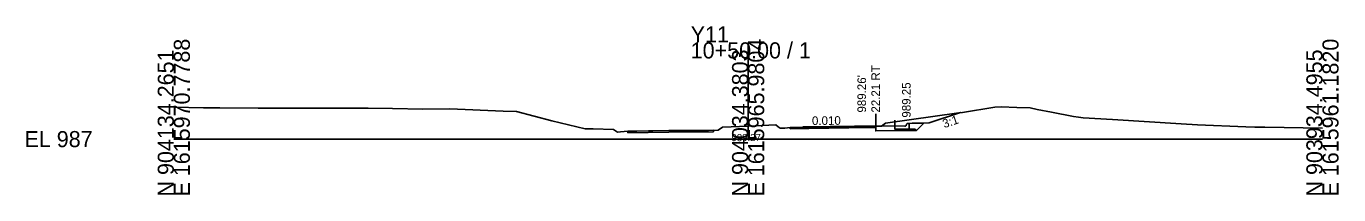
# Model space of a CAD drawing. Extents: x -26 to 203, y -10 to 2019.
# Drawn here: x -25.7 to 202.8, y 490.3 to 519.7 of the extents above; entities that cross this region are included whole.
import ezdxf

# ---------------------------------------------------------------- set-up
doc = ezdxf.new("R2010")
doc.units = 0
for name, color, linetype in [('Exist Cross Section Cell', 7, 'Continuous'), ('Exist XS Center Line Elevation Label', 7, 'Continuous'), ('Exist XS Ground Line', 7, 'Continuous'), ('Prop XS Dump Level', 7, 'Continuous'), ('Prop XS Earthwork Shape', 7, 'Continuous'), ('Prop XS EOT Tick Mark', 7, 'Continuous'), ('Prop XS Finish Grade', 7, 'Continuous'), ('Prop XS Finish Grade CurbGutter', 7, 'Continuous'), ('Prop XS Finish Grade Earthwork', 7, 'Continuous'), ('Prop XS Finish Grade Pavement', 7, 'Continuous'), ('Prop XS Hydro Elevations', 7, 'Continuous'), ('Prop XS Pvmt Edge Slope', 7, 'Continuous'), ('Prop XS Side Slope Text', 7, 'Continuous'), ('Prop XS Subgrade CurbGutter', 7, 'Continuous'), ('Prop XS Subgrade Earthwork', 7, 'Continuous')]:
    doc.layers.add(name, color=color, linetype=linetype)

msp = doc.modelspace()

# ---------------------------------------------------------------- linework, layer by layer
at = {"layer": 'Exist Cross Section Cell'}
for p, q in [((100, 500), (100, 516.85)), ((0, 500), (100, 500)), ((100, 500), (200, 500))]:
    msp.add_line(p, q, dxfattribs=at)
at = {"layer": 'Exist XS Ground Line'}
for p, q in [((0, 505.57), (5.16, 505.47)), ((5.16, 505.47), (8.01, 505.45)), ((8.01, 505.45), (14.71, 505.41)), ((14.71, 505.41), (18.03, 505.38)), ((18.03, 505.38), (21.67, 505.38)), ((21.67, 505.38), (28.04, 505.39)), ((28.04, 505.39), (33.82, 505.38)), ((33.82, 505.38), (38.05, 505.34)), ((38.05, 505.34), (43.37, 505.23)), ((43.37, 505.23), (48.06, 505.25)), ((48.06, 505.25), (57.33, 504.87)), ((137.34, 504.65), (142.98, 505.56)), ((142.98, 505.56), (144.07, 505.62)), ((144.07, 505.62), (146.78, 505.52)), ((146.78, 505.52), (149.12, 505.42)), ((149.12, 505.42), (150.33, 505.18)), ((150.33, 505.18), (152.8, 504.69)), ((57.33, 504.87), (59.65, 504.79)), ((59.65, 504.79), (65.82, 503.19)), ((65.82, 503.19), (71.65, 501.8)), ((123.25, 502.27), (123.93, 502.79)), ((123.93, 502.79), (136.66, 504.59)), ((136.66, 504.59), (137.34, 504.65)), ((152.8, 504.69), (156.67, 503.94)), ((156.67, 503.94), (157.55, 503.8)), ((157.55, 503.8), (158.33, 503.68)), ((158.33, 503.68), (163.46, 503.39)), ((163.46, 503.39), (175.39, 502.67)), ((71.65, 501.8), (73.02, 501.76)), ((73.02, 501.76), (76.57, 501.66)), ((76.57, 501.66), (77.25, 501.2)), ((77.25, 501.2), (77.75, 501.24)), ((77.75, 501.24), (79.04, 501.36)), ((79.04, 501.36), (80.63, 501.39)), ((80.63, 501.39), (86.21, 501.47)), ((86.21, 501.47), (93.08, 501.5)), ((93.08, 501.5), (94.81, 501.55)), ((94.81, 501.55), (95.52, 502.06)), ((95.52, 502.06), (100, 502.27)), ((100, 502.27), (104.84, 502.49)), ((104.84, 502.49), (105.22, 502.16)), ((105.22, 502.16), (105.59, 501.92)), ((105.59, 501.92), (106.37, 501.93)), ((106.37, 501.93), (107.33, 502.02)), ((107.33, 502.02), (110.58, 502.09)), ((110.58, 502.09), (114.26, 502.21)), ((114.26, 502.21), (118.54, 502.23)), ((118.54, 502.23), (121.5, 502.26)), ((121.5, 502.26), (122.21, 502.27)), ((122.21, 502.27), (123.25, 502.27)), ((175.39, 502.67), (178.22, 502.5)), ((178.22, 502.5), (186.67, 502.13)), ((186.67, 502.13), (188.23, 502.09)), ((188.23, 502.09), (189.95, 502.05)), ((189.95, 502.05), (200, 501.93))]:
    msp.add_line(p, q, dxfattribs=at)
at = {"layer": 'Prop XS Dump Level'}
msp.add_line((125.55, 502.3), (109.55, 502.14), dxfattribs=at)
at = {"layer": 'Prop XS Earthwork Shape'}
for points in [[(130.59, 502.79), (131.55, 502.81), (136.96, 504.61), (136.66, 504.59), (123.93, 502.79), (123.25, 502.27), (122.21, 502.27), (122.21, 501.43), (129.3, 501.5), (129.05, 501.75), (128.05, 501.74), (125.55, 501.72), (125.55, 502.3), (127.3, 502.24), (127.43, 502.27), (127.52, 502.36), (127.59, 502.61), (127.68, 502.7), (127.8, 502.74), (128.05, 502.74), (128.59, 502.75)], [(129.05, 501.75), (129.3, 501.5), (130.59, 502.79), (128.59, 502.75), (128.05, 502.74), (128.05, 501.74)], [(128.05, 501.74), (128.05, 502.74), (127.8, 502.74), (127.68, 502.7), (127.59, 502.61), (127.52, 502.36), (127.43, 502.27), (127.3, 502.24), (125.55, 502.3), (125.55, 501.72)]]:
    msp.add_lwpolyline(points, close=True, dxfattribs=at)
at = {"layer": 'Prop XS EOT Tick Mark'}
msp.add_line((125.55, 502.3), (125.55, 503.3), dxfattribs=at)
at = {"layer": 'Prop XS Finish Grade'}
msp.add_line((128.05, 502.74), (130.59, 502.79), dxfattribs=at)
at = {"layer": 'Prop XS Finish Grade CurbGutter'}
for p, q in [((125.55, 502.3), (127.3, 502.24)), ((127.3, 502.24), (127.43, 502.27)), ((127.43, 502.27), (127.52, 502.36)), ((127.52, 502.36), (127.59, 502.61)), ((127.59, 502.61), (127.68, 502.7)), ((127.8, 502.74), (127.68, 502.7)), ((128.05, 502.74), (127.8, 502.74))]:
    msp.add_line(p, q, dxfattribs=at)
at = {"layer": 'Prop XS Finish Grade Earthwork'}
for p, q in [((128.59, 502.75), (131.55, 502.81)), ((131.55, 502.81), (136.96, 504.61))]:
    msp.add_line(p, q, dxfattribs=at)
at = {"layer": 'Prop XS Finish Grade Pavement'}
for p, q in [((79.04, 501.36), (86.21, 501.47)), ((79.04, 501.36), (79.04, 501.11)), ((79.04, 501.11), (86.21, 501.22)), ((86.21, 501.47), (93.94, 501.53)), ((86.21, 501.22), (93.95, 501.28)), ((93.95, 501.28), (93.94, 501.53)), ((110.58, 502.09), (107.33, 502.02)), ((107.33, 502.02), (107.34, 501.77)), ((110.59, 501.84), (107.34, 501.77)), ((117.55, 502.22), (110.58, 502.09)), ((117.56, 501.97), (110.59, 501.84)), ((125.55, 502.29), (117.55, 502.22)), ((122.21, 502.01), (117.56, 501.97))]:
    msp.add_line(p, q, dxfattribs=at)
at = {"layer": 'Prop XS Hydro Elevations'}
msp.add_line((122.21, 502.27), (122.21, 504.38), dxfattribs=at)
at = {"layer": 'Prop XS Pvmt Edge Slope'}
for p, q in [((128.05, 501.74), (129.05, 501.75)), ((129.05, 501.75), (129.3, 501.5))]:
    msp.add_line(p, q, dxfattribs=at)
at = {"layer": 'Prop XS Subgrade CurbGutter'}
for p, q in [((125.55, 502.3), (125.55, 501.72)), ((125.55, 501.72), (128.05, 501.74)), ((128.05, 501.74), (128.05, 502.74))]:
    msp.add_line(p, q, dxfattribs=at)
at = {"layer": 'Prop XS Subgrade Earthwork'}
for p, q in [((129.3, 501.5), (130.59, 502.79)), ((122.21, 502.27), (122.21, 501.43)), ((122.21, 501.43), (129.3, 501.5))]:
    msp.add_line(p, q, dxfattribs=at)

# ---------------------------------------------------------------- texts
at = {"layer": 'Exist Cross Section Cell'}
for s, p in [('Y11', (90, 516.85)), ('10+50.00 / 1', (90, 514.05)), ('EL 987', (-26, 498.6))]:
    msp.add_text(s, height=2.8, dxfattribs=at).set_placement(p)
for s, p in [('E 1615970.7788', (2.8, 490)), ('E 1615965.9804', (102.8, 490)), ('E 1615961.1820', (202.8, 490)), ('N 904134.2651', (0, 490)), ('N 904034.3803', (100, 490)), ('N 903934.4955', (200, 490))]:
    msp.add_text(s, height=2.8, rotation=90, dxfattribs=at).set_placement(p)
at = {"layer": 'Exist XS Center Line Elevation Label'}
msp.add_text('989.27', height=1.25, dxfattribs=at).set_placement((97.1, 499.64))
at = {"layer": 'Prop XS Hydro Elevations'}
for s, p in [('22.21 RT', (122.96, 504.62)), ("989.26'", (120.53, 504.62)), ('989.25', (128.3, 503.74))]:
    msp.add_text(s, height=1.5, rotation=90, dxfattribs=at).set_placement(p)
at = {"layer": 'Prop XS Side Slope Text'}
for s, rotation, p in [('0.010', 0.5729, (111.12, 502.45)), ('3:1', 18.4349, (134.14, 501.9))]:
    msp.add_text(s, height=1.5, rotation=rotation, dxfattribs=at).set_placement(p)

doc.saveas('drawing.dxf')
